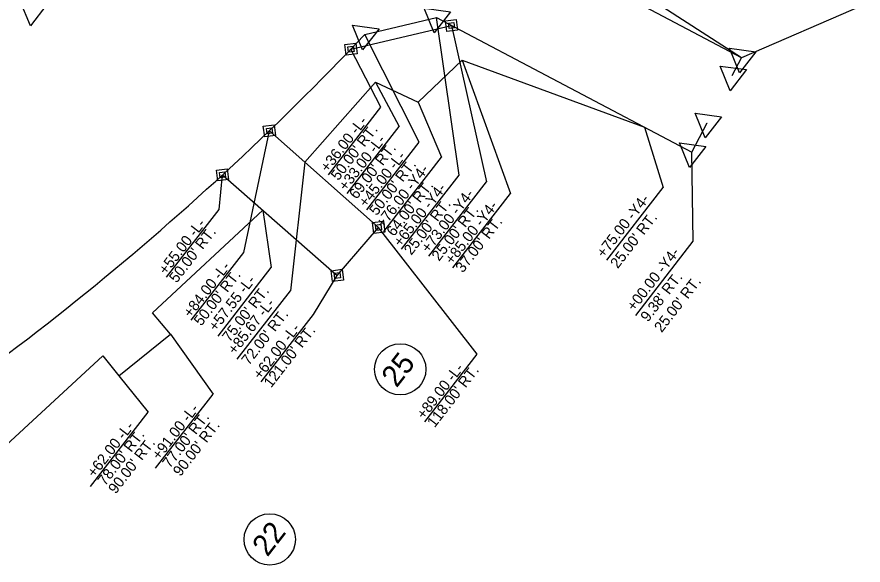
# Model space of a CAD drawing. Extents: x 2010883 to 2014849, y 442000 to 447413.
# Drawn here: x 2014042 to 2014437.7, y 445042 to 445298.5 of the extents above; entities that cross this region are included whole.
import ezdxf

# ---------------------------------------------------------------- set-up
doc = ezdxf.new("R2010")
doc.units = 0
for name, color, linetype in [('Prop Easement Construction', 7, 'Continuous'), ('Prop Easement Construction Station Offsets', 7, 'Continuous'), ('Prop Easement Permanent Utility', 7, 'Continuous'), ('Prop Easement Permanent Utility Station Offsets', 7, 'Continuous'), ('Prop Parcel Number CELL', 7, 'Continuous'), ('Prop Parcel Number Text', 7, 'Continuous'), ('Prop ROW Marker CELL', 7, 'Continuous'), ('Prop ROW Permanent Easement CELL', 7, 'Continuous'), ('Prop ROW RW Lines', 7, 'Continuous'), ('Prop ROW Station Offsets', 7, 'Continuous')]:
    doc.layers.add(name, color=color, linetype=linetype)

msp = doc.modelspace()

# ---------------------------------------------------------------- linework, layer by layer
at = {"layer": 'Prop Easement Construction'}
for p, q in [((2014380.88, 445279.41), (2014301.58, 445330.55)), ((2014229.68, 445258.57), (2014250.24, 445278.25)), ((2014250.24, 445278.25), (2014335.44, 445246.86)), ((2014176.59, 445230.6), (2014209.74, 445268.01)), ((2014209.74, 445268.01), (2014229.68, 445258.57)), ((2014105.43, 445160.06), (2014157.05, 445208.02)), ((2014113.75, 445150.07), (2014105.43, 445160.06)), ((2014089.71, 445130.49), (2014113.75, 445150.07)), ((2013997.94, 445062.16), (2014082.24, 445139.88)), ((2014082.24, 445139.88), (2014089.71, 445130.49))]:
    msp.add_line(p, q, dxfattribs=at)
at = {"layer": 'Prop Easement Construction Station Offsets'}
for p, q in [((2014250.24, 445278.25), (2014272.75, 445215.85)), ((2014209.74, 445268.01), (2014220.76, 445247.24)), ((2014229.68, 445258.57), (2014240.5, 445232.85)), ((2014196.39, 445215.8), (2014220.76, 445247.24)), ((2014335.44, 445246.86), (2014344.28, 445218.64)), ((2014213.53, 445198.08), (2014240.5, 445232.85)), ((2014176.59, 445230.6), (2014169.92, 445170.38)), ((2014245.78, 445181.08), (2014272.75, 445215.85)), ((2014317.92, 445184.67), (2014344.28, 445218.64)), ((2014157.05, 445208.02), (2014160.91, 445181.21)), ((2014136.04, 445149.15), (2014160.91, 445181.21)), ((2014145.05, 445138.31), (2014169.92, 445170.38)), ((2014113.75, 445150.07), (2014133.74, 445122.02)), ((2014089.71, 445130.49), (2014103.43, 445113.58)), ((2014106.77, 445087.25), (2014133.74, 445122.02)), ((2014076.47, 445078.81), (2014103.43, 445113.58))]:
    msp.add_line(p, q, dxfattribs=at)
at = {"layer": 'Prop Easement Permanent Utility'}
for p, q in [((2014198.21, 445283.44), (2014245.23, 445294.46)), ((2014211.14, 445200.03), (2014160.07, 445245.23)), ((2014138.14, 445224.59), (2014191.83, 445177.55)), ((2014191.83, 445177.55), (2014211.14, 445200.03))]:
    msp.add_line(p, q, dxfattribs=at)
at = {"layer": 'Prop Easement Permanent Utility Station Offsets'}
for p, q in [((2014245.23, 445294.46), (2014261.63, 445221.33)), ((2014212.16, 445256.26), (2014198.21, 445283.44)), ((2014187.64, 445224.65), (2014212.16, 445256.26)), ((2014148.06, 445188.2), (2014160.07, 445245.23)), ((2014136.53, 445208.32), (2014138.14, 445224.59)), ((2014234.66, 445186.57), (2014261.63, 445221.33)), ((2014112.01, 445176.71), (2014136.53, 445208.32)), ((2014257.19, 445140.64), (2014211.14, 445200.03)), ((2014123.54, 445156.59), (2014148.06, 445188.2)), ((2014180.73, 445159.29), (2014191.83, 445177.55)), ((2014156.21, 445127.68), (2014180.73, 445159.29)), ((2014232.68, 445109.03), (2014257.19, 445140.64))]:
    msp.add_line(p, q, dxfattribs=at)
at = {"layer": 'Prop Parcel Number CELL'}
for p, q in [((2014221.27, 445133.59), (2014221.27, 445133.59)), ((2014160.21, 445053.97), (2014160.21, 445053.97))]:
    msp.add_line(p, q, dxfattribs=at)
for centre in [(2014221.27, 445133.59), (2014160.21, 445053.97)]:
    msp.add_circle(centre, 12, dxfattribs=at)
at = {"layer": 'Prop ROW Marker CELL'}
for p, q in [((2014238.15, 445298.2), (2014238.15, 445298.2)), ((2014245.23, 445294.46), (2014245.23, 445294.46)), ((2014204.66, 445290.21), (2014204.66, 445290.21)), ((2014198.21, 445283.44), (2014198.21, 445283.44)), ((2014380.88, 445279.41), (2014380.88, 445279.41)), ((2014376.51, 445271.12), (2014376.51, 445271.12)), ((2014364.84, 445249.01), (2014364.84, 445249.01)), ((2014160.07, 445245.23), (2014160.07, 445245.23)), ((2014357.55, 445235.19), (2014357.55, 445235.19)), ((2014138.14, 445224.59), (2014138.14, 445224.59)), ((2014211.14, 445200.03), (2014211.14, 445200.03)), ((2014191.83, 445177.55), (2014191.83, 445177.55))]:
    msp.add_line(p, q, dxfattribs=at)
for points in [[(2014048.28, 445294.41), (2014043.58, 445305.96), (2014055.94, 445304.28)], [(2014237.17, 445291.05), (2014232.46, 445302.61), (2014244.83, 445300.93)], [(2014203.67, 445283.07), (2014198.97, 445294.62), (2014211.33, 445292.94)], [(2014379.9, 445272.27), (2014375.19, 445283.83), (2014387.56, 445282.15)], [(2014375.52, 445263.98), (2014370.82, 445275.54), (2014383.18, 445273.86)], [(2014363.85, 445241.86), (2014359.15, 445253.42), (2014371.51, 445251.74)], [(2014356.56, 445228.05), (2014351.86, 445239.6), (2014364.22, 445237.92)]]:
    msp.add_lwpolyline(points, close=True, dxfattribs=at)
at = {"layer": 'Prop ROW Permanent Easement CELL'}
for points in [[(2014242.38, 445296.67), (2014247.43, 445297.31), (2014248.07, 445292.26), (2014243.02, 445291.62)], [(2014243.8, 445295.57), (2014246.33, 445295.89), (2014246.65, 445293.36), (2014244.12, 445293.04)], [(2014195.37, 445285.65), (2014200.42, 445286.29), (2014201.06, 445281.24), (2014196.01, 445280.6)], [(2014196.79, 445284.55), (2014199.32, 445284.87), (2014199.64, 445282.34), (2014197.11, 445282.02)], [(2014157.22, 445247.44), (2014162.27, 445248.07), (2014162.91, 445243.02), (2014157.86, 445242.38)], [(2014158.64, 445246.33), (2014161.17, 445246.65), (2014161.49, 445244.13), (2014158.96, 445243.81)], [(2014135.29, 445226.8), (2014140.34, 445227.43), (2014140.98, 445222.38), (2014135.93, 445221.74)], [(2014136.71, 445225.69), (2014139.24, 445226.01), (2014139.56, 445223.49), (2014137.03, 445223.17)], [(2014208.3, 445202.23), (2014213.35, 445202.87), (2014213.99, 445197.82), (2014208.94, 445197.18)], [(2014209.72, 445201.13), (2014212.25, 445201.45), (2014212.56, 445198.92), (2014210.04, 445198.6)], [(2014188.99, 445179.75), (2014194.04, 445180.39), (2014194.68, 445175.34), (2014189.63, 445174.7)], [(2014190.41, 445178.65), (2014192.94, 445178.97), (2014193.26, 445176.44), (2014190.73, 445176.12)]]:
    msp.add_lwpolyline(points, close=True, dxfattribs=at)
at = {"layer": 'Prop ROW RW Lines'}
for p, q in [((2014380.88, 445279.41), (2014261.49, 445342.42)), ((2014204.66, 445290.21), (2014238.15, 445298.2)), ((2014238.15, 445298.2), (2014357.55, 445235.19)), ((2014376.51, 445271.12), (2014380.88, 445279.41)), ((2014357.55, 445235.19), (2014364.84, 445249.01))]:
    msp.add_line(p, q, dxfattribs=at)
msp.add_arc((2013223.9, 446217.91), 1350, 300.98467, 316.59253, dxfattribs=at)
at = {"layer": 'Prop ROW Station Offsets'}
for p, q in [((2014437.69, 445304.01), (2014380.88, 445279.41)), ((2014248.76, 445224.52), (2014238.15, 445298.2)), ((2014230.11, 445239.85), (2014204.66, 445290.21)), ((2014205.59, 445208.25), (2014230.11, 445239.85)), ((2014358.31, 445193.49), (2014357.55, 445235.19)), ((2014221.8, 445189.75), (2014248.76, 445224.52)), ((2014331.35, 445158.72), (2014358.31, 445193.49))]:
    msp.add_line(p, q, dxfattribs=at)

# ---------------------------------------------------------------- texts
at = {"layer": 'Prop Easement Construction Station Offsets'}
for s, p in [('+33.00 -L-', (2014195.91, 445216.69)), ("69.00' RT.", (2014200.85, 445212.86)), ('+76.00 -Y4-', (2014213.36, 445199.27)), ("64.00' RT.", (2014218.3, 445195.44)), ('+85.00 -Y4-', (2014245.61, 445182.27)), ('+75.00 -Y4-', (2014316.54, 445185.4)), ("37.00' RT.", (2014250.55, 445178.44)), ("25.00' RT.", (2014322.96, 445180.42)), ('+57.55 -L-', (2014135.07, 445150.96)), ("75.00' RT.", (2014141.49, 445145.98)), ('+85.67 -L-', (2014144.08, 445140.12)), ("72.00' RT.", (2014150.5, 445135.14)), ('+91.00 -L-', (2014108.57, 445090.81)), ("77.00' RT.", (2014113.51, 445086.98)), ("90.00' RT.", (2014118.45, 445083.15)), ('+62.00 -L-', (2014078.31, 445082.6)), ("78.00' RT.", (2014083.25, 445078.77)), ("90.00' RT.", (2014088.19, 445074.94))]:
    msp.add_text(s, height=5, rotation=52.2051, dxfattribs=at).set_placement(p)
at = {"layer": 'Prop Easement Permanent Utility Station Offsets'}
for s, p in [('+36.00 -L-', (2014187.36, 445225.43)), ("50.00' RT.", (2014192.3, 445221.59)), ('+73.00 -Y4-', (2014234.49, 445187.75)), ("25.00' RT.", (2014239.43, 445183.92)), ('+55.00 -L-', (2014111.73, 445177.49)), ("50.00' RT.", (2014116.67, 445173.66)), ('+84.00 -L-', (2014123.26, 445157.37)), ("50.00' RT.", (2014128.2, 445153.54)), ('+62.00 -L-', (2014155.93, 445128.46)), ("121.00' RT.", (2014160.87, 445124.63)), ('+89.00 -L-', (2014232.4, 445109.81)), ("118.00' RT.", (2014237.33, 445105.98))]:
    msp.add_text(s, height=5, rotation=52.2051, dxfattribs=at).set_placement(p)
at = {"layer": 'Prop Parcel Number Text'}
for s, p in [('25', (2014219.57, 445124.63)), ('22', (2014159.14, 445045.48))]:
    msp.add_text(s, height=10, rotation=52.2051, dxfattribs=at).set_placement(p)
at = {"layer": 'Prop ROW Station Offsets'}
for s, p in [('+45.00 -L-', (2014205.31, 445209.02)), ("50.00' RT.", (2014210.25, 445205.19)), ('+65.00 -Y4-', (2014221.51, 445190.53)), ("25.00' RT.", (2014226.45, 445186.7)), ('+00.00 -Y4-', (2014330.66, 445160.43)), ("9.38' RT.", (2014337.08, 445155.45)), ("25.00' RT.", (2014343.5, 445150.47))]:
    msp.add_text(s, height=5, rotation=52.2051, dxfattribs=at).set_placement(p)

doc.saveas('drawing.dxf')
